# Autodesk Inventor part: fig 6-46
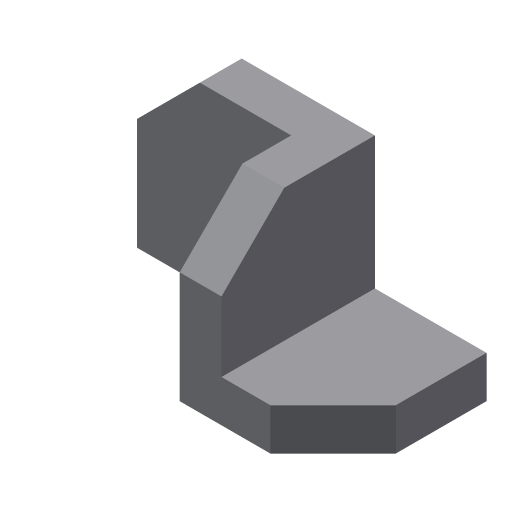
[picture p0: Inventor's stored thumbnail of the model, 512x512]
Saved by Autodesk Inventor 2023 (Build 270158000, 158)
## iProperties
Created: 2001-12
Part Number: fig 6-46
Document SubType Name: Modeling
Designer: Renu Muthoo
Density: 1 g/cm^3
Material: Generic
Appearance: Default
Control State: 0
Master: False
Checked Out: False
Shininess: 77.0
Angle Display Precision: 2
Document Length Units: 11269
Document Angle Units: 11279
Document Time Units: 11290
Document Mass Units: 11283
Document Length Units Precision: 3
Document Angle Units Precision: 2
Density: 0.0
Volumn: 0.0
Area: 0.0
PropertySet Name: Model Information
Author: Renu Muthoo
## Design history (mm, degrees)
node "Sketch1"
sketch "Sketch2"
  geometry: L1 (16.794, 27.142)-(16.794, -22.858); L2 (16.794, -22.858)-(-27.206, -22.858); L3 (-27.206, -22.858)-(-27.206, -10.858); L4 (-27.206, -10.858)-(4.794, -10.858); L5 (4.794, -10.858)-(4.794, 27.142); L6 (4.794, 27.142)-(16.794, 27.142)
  constraints: 12 end point, 4 parallel, 2 perpendicular, 1 vertical
  dimensions: "d0" = 44 distance of L1.end L2.end; "d1" = 50 distance of L1.start L1.end; "d2" = 12 distance of L2.end L3.end
extrude "Extrusion1" new body sketch "Sketch2" distance "d3" = 44; taper "d4" = 0 deg
sketch "Sketch4"
  geometry: L1 (-16.794, -27.142)-(-16.794, 22.858) reference; L2 (27.206, 22.858)-(27.206, 10.858) reference; L3 (-16.794, -27.142)-(-61.001, -27.142); L4 (-61.001, -27.142)-(-61.001, 22.858); L5 (-61.001, 22.858)-(-16.794, 22.858)
  constraints: 6 end point, 2 perpendicular, 1 parallel
extrude "Extrusion3" join sketch "Sketch4" distance "d13" = 12; taper "d14" = 0 deg
chamfer "Chamfer3" distance "d15" = 18; stored, may be unused: second distance "d16" = 2, angle "d17" = 45 deg
body "Solid1"
